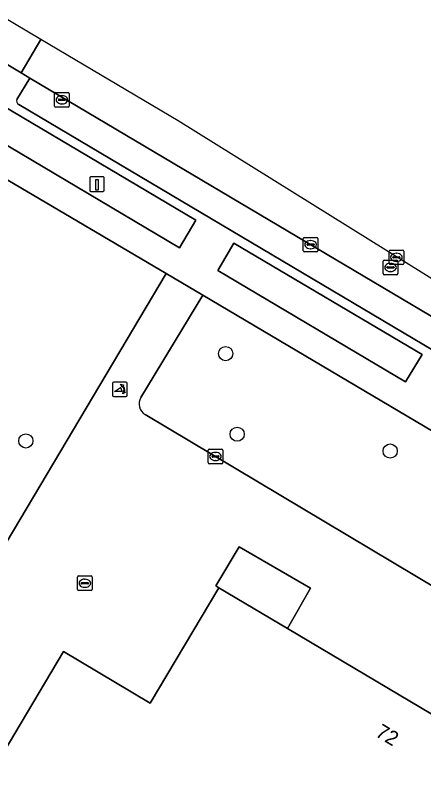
# Model space of a CAD drawing. Extents: x 163266 to 164362, y 381528 to 382286.
# Drawn here: x 163389.6 to 163417.6, y 381777.8 to 381831.2 of the extents above; entities that cross this region are included whole.
import ezdxf

# ---------------------------------------------------------------- set-up
doc = ezdxf.new("R2010")
doc.units = 0
for name, color, linetype in [('IMGEO_Boom', 7, 'Continuous'), ('IMGEO_Groenvoorziening', 7, 'Continuous'), ('IMGEO_Kolk', 7, 'Continuous'), ('IMGEO_Laadpaal', 7, 'Continuous'), ('IMGEO_Loofbos', 7, 'Continuous'), ('IMGEO_Pand', 7, 'Continuous'), ('IMGEO_Pand_nummerreeks', 7, 'Continuous'), ('IMGEO_Parkeervlak_open', 7, 'Continuous'), ('IMGEO_Poller', 7, 'Continuous'), ('IMGEO_Rijbaan_lokaal_gesloten', 7, 'Continuous'), ('IMGEO_Rijbaan_lokaal_open', 7, 'Continuous'), ('IMGEO_Rioolput', 7, 'Continuous'), ('IMGEO_Voetpad_open', 7, 'Continuous')]:
    doc.layers.add(name, color=color, linetype=linetype)

msp = doc.modelspace()

# ---------------------------------------------------------------- linework, layer by layer
at = {"layer": 'IMGEO_Boom'}
for centre in [(163403.988, 381807.993), (163404.781, 381802.45), (163390.263, 381801.991), (163415.289, 381801.289)]:
    msp.add_circle(centre, 0.489, dxfattribs=at)
at = {"layer": 'IMGEO_Groenvoorziening'}
for points in [[(163387.549, 381823.158), (163400.823, 381815.258), (163401.941, 381817.177), (163388.655, 381825.047)], [(163404.552, 381815.601), (163403.448, 381813.704), (163416.35, 381806.043), (163417.486, 381807.924)], [(163403.519, 381791.894), (163408.23, 381789.092), (163409.824, 381791.863), (163404.927, 381794.71), (163403.313, 381792.017)]]:
    msp.add_lwpolyline(points, close=True, dxfattribs=at)
for points in [[(163427.301, 381787.402), (163431.611, 381794.694), (163402.419, 381812.014), (163398.158, 381804.974)], [(163398.45, 381803.806), (163426.308, 381787.151)]]:
    msp.add_lwpolyline(points, dxfattribs=at)
msp.add_arc((163398.884, 381804.535), 0.848, 148.8424, 239.2301, dxfattribs=at)
at = {"layer": 'IMGEO_Kolk'}
for p, q in [((163392.24, 381825.024), (163392.24, 381825.876)), ((163392.315, 381825.95), (163393.167, 381825.95)), ((163393.241, 381825.876), (163393.241, 381825.024)), ((163392.499, 381825.444), (163392.499, 381825.456)), ((163392.937, 381825.407), (163392.539, 381825.407)), ((163392.542, 381825.493), (163392.94, 381825.493)), ((163392.728, 381825.73), (163392.753, 381825.73)), ((163392.983, 381825.456), (163392.983, 381825.444)), ((163393.167, 381824.95), (163392.315, 381824.95)), ((163392.751, 381825.17), (163392.726, 381825.17)), ((163409.324, 381815.064), (163409.324, 381815.916)), ((163409.399, 381815.99), (163410.251, 381815.99)), ((163409.812, 381815.77), (163409.837, 381815.77)), ((163410.325, 381815.916), (163410.325, 381815.064)), ((163409.583, 381815.484), (163409.583, 381815.496)), ((163410.021, 381815.447), (163409.623, 381815.447)), ((163409.626, 381815.533), (163410.024, 381815.533)), ((163409.835, 381815.21), (163409.81, 381815.21)), ((163410.067, 381815.496), (163410.067, 381815.484)), ((163410.251, 381814.99), (163409.399, 381814.99)), ((163402.789, 381800.497), (163402.789, 381801.349)), ((163402.864, 381801.423), (163403.716, 381801.423)), ((163403.277, 381801.203), (163403.302, 381801.203)), ((163403.79, 381801.349), (163403.79, 381800.497)), ((163403.048, 381800.917), (163403.048, 381800.929)), ((163403.486, 381800.88), (163403.088, 381800.88)), ((163403.091, 381800.966), (163403.489, 381800.966)), ((163403.3, 381800.643), (163403.275, 381800.643)), ((163403.532, 381800.929), (163403.532, 381800.917)), ((163403.716, 381800.423), (163402.864, 381800.423)), ((163393.815, 381791.773), (163393.815, 381792.625)), ((163393.89, 381792.699), (163394.742, 381792.699)), ((163394.816, 381792.625), (163394.816, 381791.773)), ((163394.074, 381792.193), (163394.074, 381792.205)), ((163394.512, 381792.156), (163394.114, 381792.156)), ((163394.117, 381792.242), (163394.515, 381792.242)), ((163394.303, 381792.479), (163394.328, 381792.479)), ((163394.558, 381792.205), (163394.558, 381792.193)), ((163394.742, 381791.699), (163393.89, 381791.699)), ((163394.326, 381791.919), (163394.301, 381791.919))]:
    msp.add_line(p, q, dxfattribs=at)
for points in [[(163392.24, 381825.024), (163392.24, 381825.876)], [(163392.315, 381825.95), (163393.167, 381825.95)], [(163393.241, 381825.876), (163393.241, 381825.024)], [(163393.167, 381824.95), (163392.315, 381824.95)], [(163409.324, 381815.064), (163409.324, 381815.916)], [(163409.399, 381815.99), (163410.251, 381815.99)], [(163410.325, 381815.916), (163410.325, 381815.064)], [(163410.251, 381814.99), (163409.399, 381814.99)], [(163402.789, 381800.497), (163402.789, 381801.349)], [(163402.864, 381801.423), (163403.716, 381801.423)], [(163403.79, 381801.349), (163403.79, 381800.497)], [(163403.716, 381800.423), (163402.864, 381800.423)], [(163393.815, 381791.773), (163393.815, 381792.625)], [(163393.89, 381792.699), (163394.742, 381792.699)], [(163394.816, 381792.625), (163394.816, 381791.773)], [(163394.742, 381791.699), (163393.89, 381791.699)]]:
    msp.add_lwpolyline(points, dxfattribs=at)
for centre, radius, start, end in [((163392.317, 381825.874), 0.0765, 91.552, 178.448), ((163392.317, 381825.874), 0.0765, 91.552, 178.448), ((163393.165, 381825.874), 0.0765, 1.552, 88.448), ((163393.165, 381825.874), 0.0765, 1.552, 88.448), ((163392.539, 381825.453), 0.0403, 85.8775, 175.7526), ((163392.536, 381825.443), 0.0366, 178.938, 274.7102), ((163392.94, 381825.45), 0.043, 264.8664, 352.4533), ((163392.944, 381825.455), 0.0386, 1.7309, 96.639), ((163392.317, 381825.026), 0.0765, 181.552, 268.448), ((163392.317, 381825.026), 0.0765, 181.552, 268.448), ((163393.165, 381825.026), 0.0765, 271.552, 358.448), ((163393.165, 381825.026), 0.0765, 271.552, 358.448), ((163409.401, 381815.914), 0.0765, 91.552, 178.448), ((163409.401, 381815.914), 0.0765, 91.552, 178.448), ((163410.249, 381815.914), 0.0765, 1.552, 88.448), ((163410.249, 381815.914), 0.0765, 1.552, 88.448), ((163409.401, 381815.066), 0.0765, 181.552, 268.448), ((163409.401, 381815.066), 0.0765, 181.552, 268.448), ((163409.623, 381815.493), 0.0403, 85.8775, 175.7526), ((163409.62, 381815.483), 0.0366, 178.938, 274.7102), ((163410.024, 381815.49), 0.043, 264.8664, 352.4533), ((163410.028, 381815.495), 0.0386, 1.7309, 96.639), ((163410.249, 381815.066), 0.0765, 271.552, 358.448), ((163410.249, 381815.066), 0.0765, 271.552, 358.448), ((163402.866, 381801.347), 0.0765, 91.552, 178.448), ((163402.866, 381801.347), 0.0765, 91.552, 178.448), ((163403.714, 381801.347), 0.0765, 1.552, 88.448), ((163403.714, 381801.347), 0.0765, 1.552, 88.448), ((163403.088, 381800.926), 0.0403, 85.8775, 175.7526), ((163403.085, 381800.916), 0.0366, 178.938, 274.7102), ((163403.489, 381800.923), 0.043, 264.8664, 352.4533), ((163403.493, 381800.928), 0.0386, 1.7309, 96.639), ((163402.866, 381800.499), 0.0765, 181.552, 268.448), ((163402.866, 381800.499), 0.0765, 181.552, 268.448), ((163403.714, 381800.499), 0.0765, 271.552, 358.448), ((163403.714, 381800.499), 0.0765, 271.552, 358.448), ((163393.892, 381792.623), 0.0765, 91.552, 178.448), ((163393.892, 381792.623), 0.0765, 91.552, 178.448), ((163394.74, 381792.623), 0.0765, 1.552, 88.448), ((163394.74, 381792.623), 0.0765, 1.552, 88.448), ((163394.114, 381792.202), 0.0403, 85.8775, 175.7526), ((163394.111, 381792.192), 0.0366, 178.938, 274.7102), ((163394.515, 381792.199), 0.043, 264.8664, 352.4533), ((163394.519, 381792.204), 0.0386, 1.7309, 96.639), ((163393.892, 381791.775), 0.0765, 181.552, 268.448), ((163393.892, 381791.775), 0.0765, 181.552, 268.448), ((163394.74, 381791.775), 0.0765, 271.552, 358.448), ((163394.74, 381791.775), 0.0765, 271.552, 358.448)]:
    msp.add_arc(centre, radius, start, end, dxfattribs=at)
for centre, major_axis, ratio, start_param, end_param in [((163392.727, 381825.45), (-0.387, 0.002), 0.722429, 4.712389, 7.853982), ((163392.752, 381825.45), (-0.39, 0.002), 0.717154, 1.570796, 4.712389), ((163409.811, 381815.49), (-0.387, 0.002), 0.722429, 4.712389, 7.853982), ((163409.836, 381815.49), (-0.39, 0.002), 0.717154, 1.570796, 4.712389), ((163403.276, 381800.923), (-0.387, 0.002), 0.722429, 4.712389, 7.853982), ((163403.301, 381800.923), (-0.39, 0.002), 0.717154, 1.570796, 4.712389), ((163394.302, 381792.199), (-0.387, 0.002), 0.722429, 4.712389, 7.853982), ((163394.327, 381792.199), (-0.39, 0.002), 0.717154, 1.570796, 4.712389)]:
    msp.add_ellipse(centre, major_axis=major_axis, ratio=ratio, start_param=start_param, end_param=end_param, dxfattribs=at)
at = {"layer": 'IMGEO_Laadpaal'}
for p, q in [((163394.652, 381820.068), (163394.652, 381819.227)), ((163394.652, 381820.068), (163394.652, 381819.227)), ((163395.568, 381820.152), (163394.727, 381820.152)), ((163395.568, 381820.152), (163394.727, 381820.152)), ((163395.652, 381819.236), (163395.652, 381820.077)), ((163395.652, 381819.236), (163395.652, 381820.077)), ((163394.736, 381819.152), (163395.577, 381819.152)), ((163394.736, 381819.152), (163395.577, 381819.152))]:
    msp.add_line(p, q, dxfattribs=at)
msp.add_lwpolyline([(163395.067, 381819.965), (163395.227, 381819.965), (163395.227, 381819.232), (163395.067, 381819.232), (163395.067, 381819.965)], dxfattribs=at)
for centre, start, end in [((163394.73, 381820.074), 92.4484, 184.2845), ((163394.73, 381820.074), 92.4484, 184.2845), ((163395.574, 381820.074), 2.4484, 94.2845), ((163395.574, 381820.074), 2.4484, 94.2845), ((163394.73, 381819.23), 182.4484, 274.2845), ((163394.73, 381819.23), 182.4484, 274.2845), ((163395.574, 381819.23), 272.4484, 4.2845), ((163395.574, 381819.23), 272.4484, 4.2845)]:
    msp.add_arc(centre, 0.0779, start, end, dxfattribs=at)
at = {"layer": 'IMGEO_Loofbos'}
msp.add_lwpolyline([(163377.703, 381776.118), (163374.433, 381778.124), (163378.164, 381784.447), (163381.439, 381782.438), (163381.642, 381782.782), (163399.897, 381813.506), (163383.38, 381823.245), (163360.112, 381781.892), (163342.168, 381750), (163336.563, 381740.039), (163340.355, 381738.083), (163358.538, 381743.692), (163362.266, 381750)], close=True, dxfattribs=at)
at = {"layer": 'IMGEO_Pand'}
msp.add_lwpolyline([(163428.402, 381766.025), (163428.501, 381766.192), (163424.907, 381768.33), (163427.079, 381771.982), (163429.671, 381776.339), (163419.677, 381782.283), (163408.23, 381789.092), (163403.519, 381791.894), (163398.799, 381783.958), (163392.846, 381787.499), (163387.823, 381779.056), (163384.314, 381781.143), (163384.11, 381780.799), (163380.357, 381774.49), (163370.889, 381758.571), (163374.444, 381756.457), (163370.601, 381750), (163369.529, 381748.198), (163394.486, 381733.35), (163397.58, 381731.509), (163398.374, 381732.844), (163405.983, 381728.318), (163418.874, 381750)], close=True, dxfattribs=at)
at = {"layer": 'IMGEO_Parkeervlak_open'}
for points in [[(163390.527, 381826.932), (163389.646, 381825.48)], [(163429.702, 381801.693), (163430.544, 381803.188), (163390.527, 381826.932)], [(163389.782, 381825.131), (163429.369, 381801.606)]]:
    msp.add_lwpolyline(points, dxfattribs=at)
msp.add_arc((163389.909, 381825.382), 0.281, 159.4722, 243.108, dxfattribs=at)
at = {"layer": 'IMGEO_Poller'}
for p, q in [((163397.122, 381806.033), (163396.314, 381806.033)), ((163397.122, 381806.033), (163396.314, 381806.033)), ((163396.22, 381805.938), (163396.22, 381805.131)), ((163396.22, 381805.938), (163396.22, 381805.131)), ((163397.216, 381805.131), (163397.216, 381805.938)), ((163397.216, 381805.131), (163397.216, 381805.938)), ((163396.314, 381805.036), (163397.122, 381805.036)), ((163396.314, 381805.036), (163397.122, 381805.036))]:
    msp.add_line(p, q, dxfattribs=at)
for points in [[(163396.855, 381805.389), (163396.342, 381805.389), (163396.772, 381805.664)], [(163396.899, 381805.762), (163396.887, 381805.689), (163396.762, 381805.894)], [(163396.762, 381805.894), (163396.993, 381805.828), (163396.922, 381805.796)], [(163396.915, 381805.217), (163396.981, 381805.448), (163397.011, 381805.38)], [(163397.047, 381805.353), (163397.119, 381805.342), (163396.915, 381805.217)]]:
    msp.add_lwpolyline(points, dxfattribs=at)
for centre, radius, start, end in [((163396.314, 381805.938), 0.0946, 90, 180), ((163396.314, 381805.938), 0.0946, 90, 180), ((163397.122, 381805.938), 0.0946, 0, 90), ((163397.122, 381805.938), 0.0946, 0, 90), ((163396.527, 381805.439), 0.332, 351.3247, 42.4854), ((163396.541, 381805.449), 0.476, 351.7527, 41.1691), ((163396.541, 381805.449), 0.516, 349.3569, 42.2912), ((163396.314, 381805.131), 0.0946, 180, 270), ((163396.314, 381805.131), 0.0946, 180, 270), ((163397.122, 381805.131), 0.0946, 270, 0), ((163397.122, 381805.131), 0.0946, 270, 0)]:
    msp.add_arc(centre, radius, start, end, dxfattribs=at)
at = {"layer": 'IMGEO_Rijbaan_lokaal_gesloten'}
msp.add_lwpolyline([(163391.302, 381829.601), (163388.531, 381831.246), (163387.176, 381828.962), (163389.944, 381827.309)], close=True, dxfattribs=at)
at = {"layer": 'IMGEO_Rijbaan_lokaal_open'}
msp.add_lwpolyline([(163432.06, 381804.479), (163400.716, 381824.015), (163391.302, 381829.601), (163389.944, 381827.309), (163390.527, 381826.932), (163430.544, 381803.188), (163431.129, 381802.872)], close=True, dxfattribs=at)
at = {"layer": 'IMGEO_Rioolput'}
for p, q in [((163415.295, 381815.115), (163416.147, 381815.115)), ((163415.22, 381814.189), (163415.22, 381815.041)), ((163415.479, 381814.609), (163415.479, 381814.621)), ((163415.917, 381814.572), (163415.519, 381814.572)), ((163415.522, 381814.658), (163415.92, 381814.658)), ((163415.708, 381814.895), (163415.733, 381814.895)), ((163415.963, 381814.621), (163415.963, 381814.609)), ((163416.221, 381815.041), (163416.221, 381814.189)), ((163414.812, 381813.496), (163414.812, 381814.348)), ((163414.887, 381814.422), (163415.739, 381814.422)), ((163416.147, 381814.115), (163415.295, 381814.115)), ((163415.3, 381814.202), (163415.325, 381814.202)), ((163415.731, 381814.335), (163415.706, 381814.335)), ((163415.813, 381814.348), (163415.813, 381813.496)), ((163415.071, 381813.916), (163415.071, 381813.928)), ((163415.509, 381813.879), (163415.111, 381813.879)), ((163415.114, 381813.965), (163415.512, 381813.965)), ((163415.323, 381813.642), (163415.298, 381813.642)), ((163415.555, 381813.928), (163415.555, 381813.916)), ((163415.739, 381813.422), (163414.887, 381813.422))]:
    msp.add_line(p, q, dxfattribs=at)
for points in [[(163415.295, 381815.115), (163416.147, 381815.115)], [(163415.22, 381814.189), (163415.22, 381815.041)], [(163416.221, 381815.041), (163416.221, 381814.189)], [(163414.812, 381813.496), (163414.812, 381814.348)], [(163414.887, 381814.422), (163415.739, 381814.422)], [(163416.147, 381814.115), (163415.295, 381814.115)], [(163415.813, 381814.348), (163415.813, 381813.496)], [(163415.739, 381813.422), (163414.887, 381813.422)]]:
    msp.add_lwpolyline(points, dxfattribs=at)
for centre, radius, start, end in [((163415.297, 381815.039), 0.0765, 91.552, 178.448), ((163415.297, 381815.039), 0.0765, 91.552, 178.448), ((163416.145, 381815.039), 0.0765, 1.552, 88.448), ((163416.145, 381815.039), 0.0765, 1.552, 88.448), ((163415.519, 381814.618), 0.0403, 85.8775, 175.7526), ((163415.516, 381814.608), 0.0366, 178.938, 274.7102), ((163415.92, 381814.615), 0.043, 264.8664, 352.4533), ((163415.924, 381814.62), 0.0386, 1.7309, 96.639), ((163414.889, 381814.346), 0.0765, 91.552, 178.448), ((163414.889, 381814.346), 0.0765, 91.552, 178.448), ((163415.297, 381814.191), 0.0765, 181.552, 268.448), ((163415.297, 381814.191), 0.0765, 181.552, 268.448), ((163415.737, 381814.346), 0.0765, 1.552, 88.448), ((163415.737, 381814.346), 0.0765, 1.552, 88.448), ((163416.145, 381814.191), 0.0765, 271.552, 358.448), ((163416.145, 381814.191), 0.0765, 271.552, 358.448), ((163414.889, 381813.498), 0.0765, 181.552, 268.448), ((163414.889, 381813.498), 0.0765, 181.552, 268.448), ((163415.111, 381813.925), 0.0403, 85.8775, 175.7526), ((163415.108, 381813.915), 0.0366, 178.938, 274.7102), ((163415.512, 381813.922), 0.043, 264.8664, 352.4533), ((163415.516, 381813.927), 0.0386, 1.7309, 96.639), ((163415.737, 381813.498), 0.0765, 271.552, 358.448), ((163415.737, 381813.498), 0.0765, 271.552, 358.448)]:
    msp.add_arc(centre, radius, start, end, dxfattribs=at)
for centre, major_axis, ratio, start_param, end_param in [((163415.707, 381814.615), (-0.387, 0.002), 0.722429, 4.712389, 7.853982), ((163415.732, 381814.615), (-0.39, 0.002), 0.717154, 1.570796, 4.712389), ((163415.299, 381813.922), (-0.387, 0.002), 0.722429, 4.712389, 7.853982), ((163415.324, 381813.922), (-0.39, 0.002), 0.717154, 1.570796, 4.712389)]:
    msp.add_ellipse(centre, major_axis=major_axis, ratio=ratio, start_param=start_param, end_param=end_param, dxfattribs=at)
at = {"layer": 'IMGEO_Voetpad_open'}
for points in [[(163389.646, 381825.48), (163390.527, 381826.932), (163389.944, 381827.309), (163387.176, 381828.962), (163386.184, 381829.549)], [(163385.772, 381829.244), (163386.645, 381828.721), (163384.446, 381825.017), (163379.528, 381827.908), (163378.549, 381826.079), (163382.696, 381823.649), (163383.38, 381823.245), (163399.897, 381813.506), (163402.419, 381812.014), (163431.611, 381794.694), (163432.904, 381793.89), (163452.241, 381782.568)], [(163429.369, 381801.606), (163389.782, 381825.131)], [(163398.158, 381804.974), (163402.419, 381812.014), (163399.897, 381813.506), (163381.642, 381782.782), (163384.314, 381781.143), (163387.823, 381779.056), (163392.846, 381787.499), (163398.799, 381783.958), (163403.519, 381791.894), (163403.313, 381792.017), (163404.927, 381794.71), (163409.824, 381791.863), (163408.23, 381789.092), (163419.677, 381782.283), (163421.296, 381784.989), (163435.757, 381776.446), (163431.512, 381769.334), (163433.067, 381768.406), (163437.283, 381775.495), (163440.815, 381773.293), (163444.609, 381771.008), (163444.821, 381770.88), (163447.13, 381774.816)], [(163426.308, 381787.151), (163398.45, 381803.806)]]:
    msp.add_lwpolyline(points, dxfattribs=at)
for points in [[(163387.549, 381823.158), (163388.655, 381825.047), (163401.941, 381817.177), (163400.823, 381815.258)], [(163404.552, 381815.601), (163417.486, 381807.924), (163416.35, 381806.043), (163403.448, 381813.704)]]:
    msp.add_lwpolyline(points, close=True, dxfattribs=at)
for centre, radius, start, end in [((163389.909, 381825.382), 0.281, 159.4722, 243.108), ((163398.884, 381804.535), 0.848, 148.8424, 239.2301)]:
    msp.add_arc(centre, radius, start, end, dxfattribs=at)

# ---------------------------------------------------------------- texts
at = {"layer": 'IMGEO_Pand_nummerreeks'}
msp.add_text('72', height=1, rotation=329.2551, dxfattribs=at).set_placement((163414.206, 381781.721))

doc.saveas('drawing.dxf')
